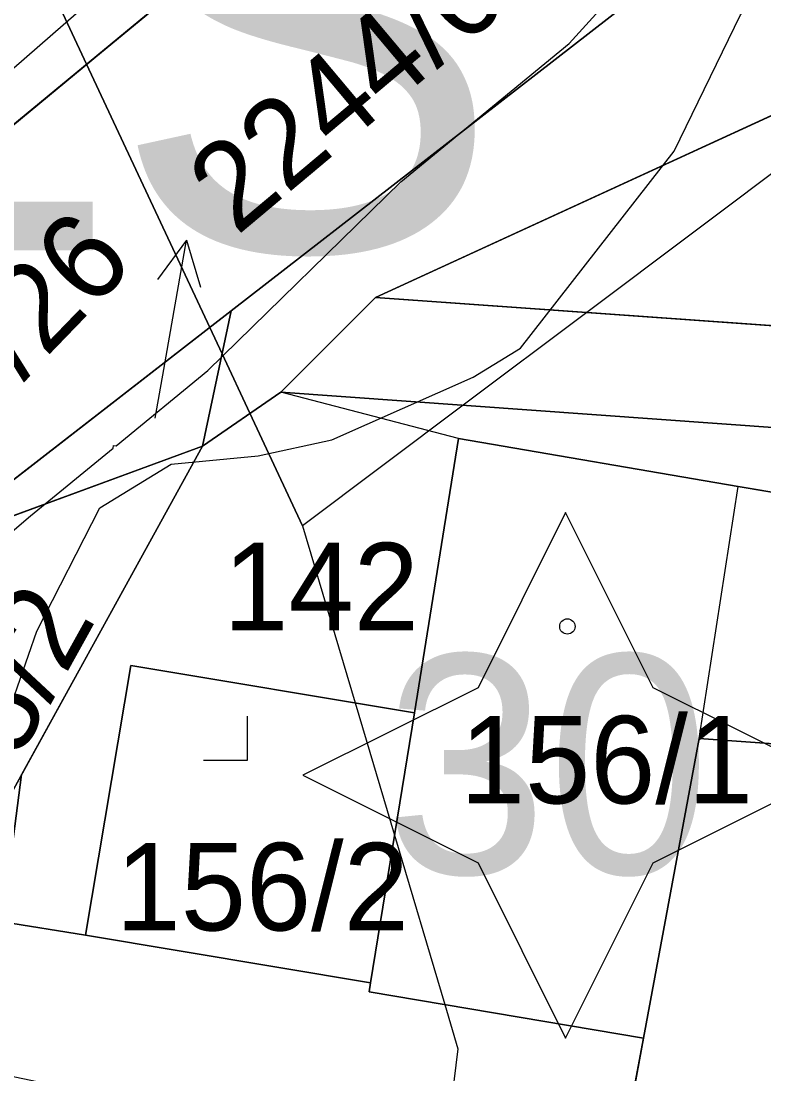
# Model space of a CAD drawing. Extents: x -706130 to -698555, y -971544 to -967260.
# Drawn here: x -704362.42 to -704345.46, y -970171.06 to -970147.02 of the extents above; entities that cross this region are included whole.
import ezdxf

# ---------------------------------------------------------------- set-up
doc = ezdxf.new("R2010")
doc.units = 0
for name, color, linetype in [('_Doplněk budov pro zastavěnost', 7, 'Continuous'), ('Architektonicky cenná stavba S', 7, 'Continuous'), ('BPEJ hranice S', 7, 'Continuous'), ('BPEJ I-II trida ochrany S', 7, 'Continuous'), ('Docházková izochrona - BUS S', 7, 'Continuous'), ('Docházková izochrona - VLAK N', 7, 'Continuous'), ('Hranice intravilán', 7, 'Continuous'), ('KN_Budovy', 7, 'Continuous'), ('KN_Budovy_cisla_domovni', 7, 'Continuous'), ('KN_Hranice_parcel', 7, 'Continuous'), ('KN_Hranice_parcel_vnitrni_kresba', 7, 'Continuous'), ('KN_Parcelni cisla', 7, 'Continuous'), ('KN_Parcelni cisla_sipky', 7, 'Continuous'), ('KN_Polygon parcely', 7, 'Continuous'), ('KN_POZEMKY_11_VODNI_PLOCHA', 7, 'Continuous'), ('KN_POZEMKY_13_ZASTAVENA PLOCHA', 7, 'Continuous'), ('KN_POZEMKY_14_OSTATNI PLOCHA', 7, 'Continuous'), ('KN_POZEMKY_7_TTP', 7, 'Continuous'), ('KN_VYUZITI_07_vodni plocha_tok prirozeny', 7, 'Continuous'), ('KN_VYUZITI_13_zastavena plocha_zboreniste', 7, 'Continuous'), ('KN_VYUZITI_23_ostatni plocha_manipulacni plocha', 7, 'Continuous'), ('KN_VYUZITI_26_ostatni plocha_jina plocha', 7, 'Continuous'), ('KN_Značky budov', 7, 'Continuous'), ('KN_Značky kultur', 7, 'Continuous'), ('Plochy smíšené obytné venkovské S', 7, 'Continuous'), ('Plochy vodní a vodnich toku S', 7, 'Continuous'), ('Plochy zeleně sídelní ostatní S', 7, 'Continuous'), ('Regulační bloky v krajině S', 7, 'Continuous'), ('Regulační bloky v krajině S  TIS', 7, 'Continuous'), ('Regulační bloky zastavěné S', 7, 'Continuous'), ('Regulační kódy zastavěné S', 7, 'Continuous'), ('Záplavové území stanovene S', 7, 'Continuous'), ('Záplavového území_aktivní zóna S', 7, 'Continuous')]:
    doc.layers.add(name, color=color, linetype=linetype)

msp = doc.modelspace()

# ---------------------------------------------------------------- linework, layer by layer
at = {"layer": '_Doplněk budov pro zastavěnost'}
for p, q in [((-704356.49, -970155.49), (-704358.28, -970156.72)), ((-704352.43, -970156.55), (-704356.49, -970155.49)), ((-704352.43, -970156.55), (-704356.49, -970155.49)), ((-704353.44, -970162.81), (-704352.43, -970156.55)), ((-704358.28, -970156.72), (-704362.406, -970164.219)), ((-704353.44, -970162.81), (-704359.91, -970161.73)), ((-704354.44, -970168.98), (-704353.44, -970162.81)), ((-704354.44, -970168.98), (-704353.44, -970162.81)), ((-704354.44, -970168.98), (-704353.44, -970162.81)), ((-704360.95, -970167.89), (-704354.44, -970168.98))]:
    msp.add_line(p, q, dxfattribs=at)
for points in [[(-704359.91, -970161.73), (-704360.95, -970167.89), (-704354.44, -970168.98)], [(-704353.44, -970162.81), (-704359.91, -970161.73), (-704360.95, -970167.89), (-704354.44, -970168.98)], [(-704360.95, -970167.89), (-704362.842, -970167.586), (-704362.406, -970164.219)], [(-704362.406, -970164.219), (-704362.842, -970167.586), (-704360.95, -970167.89)]]:
    msp.add_lwpolyline(points, dxfattribs=at)
at = {"layer": 'Architektonicky cenná stavba S'}
msp.add_lwpolyline([(-704349.987, -970158.238), (-704351.987, -970162.238), (-704355.987, -970164.238), (-704351.987, -970166.238), (-704349.987, -970170.238), (-704347.987, -970166.238), (-704343.987, -970164.238), (-704347.987, -970162.238)], close=True, dxfattribs=at)
at = {"layer": 'BPEJ hranice S'}
for points in [[(-704374.745, -970128.973), (-704371.478, -970133.132), (-704362.806, -970143.976), (-704362.45, -970144.737), (-704360.924, -970147.999), (-704358.111, -970154.01), (-704357.83, -970154.611), (-704357.193, -970155.972), (-704355.992, -970158.539), (-704354.792, -970162.584), (-704353.894, -970165.608), (-704352.747, -970169.471), (-704352.447, -970170.482), (-704352.624, -970171.915), (-704354.19, -970184.627), (-704354.367, -970186.056), (-704354.5, -970187.135), (-704355.235, -970193.101), (-704355.864, -970195.572)], [(-704322.312, -970131.353), (-704329.974, -970139.019), (-704330.011, -970139.046), (-704336.737, -970144.092), (-704339.645, -970146.274), (-704344.012, -970149.55), (-704344.613, -970150.001), (-704349.505, -970153.672), (-704352.326, -970155.788), (-704355.992, -970158.539), (-704357.193, -970155.972), (-704357.83, -970154.611), (-704358.111, -970154.01), (-704360.924, -970147.999), (-704362.45, -970144.737), (-704362.806, -970143.976), (-704371.478, -970133.132), (-704374.745, -970128.973)]]:
    msp.add_lwpolyline(points, dxfattribs=at)
at = {"layer": 'BPEJ I-II trida ochrany S'}
for p, q in [((-704346.94, -970163.4), (-704348.21, -970170.24)), ((-704341.29, -970163.8), (-704346.94, -970163.4)), ((-704348.21, -970170.24), (-704348.58, -970172.23))]:
    msp.add_line(p, q, dxfattribs=at)
at = {"layer": 'Docházková izochrona - BUS S'}
msp.add_arc((-704361.829, -969946.93), 400, 155.51821, 17.33949, dxfattribs=at)
at = {"layer": 'Docházková izochrona - VLAK N'}
msp.add_circle((-704165.451, -969778.767), 800, dxfattribs=at)
at = {"layer": 'Hranice intravilán'}
msp.add_lwpolyline([(-704412.95, -970204.59), (-704393.35, -970187.6), (-704381.73, -970177.47), (-704374.49, -970170.08), (-704373.21, -970168.89), (-704369.29, -970169.71), (-704364.61, -970159.05), (-704358.28, -970156.72), (-704356.49, -970155.49), (-704354.33, -970153.33), (-704341.43, -970147.4), (-704333.46, -970132), (-704329.78, -970132.11), (-704329.33, -970118.8)], dxfattribs=at)
at = {"layer": 'KN_Budovy'}
msp.add_lwpolyline([(-704353.44, -970162.81), (-704354.44, -970168.98), (-704354.47, -970169.18), (-704348.21, -970170.24), (-704346.94, -970163.4), (-704346.05, -970157.64), (-704352.43, -970156.55)], close=True, dxfattribs=at)
at = {"layer": 'KN_Hranice_parcel'}
for p, q in [((-704363.85, -970150.42), (-704354.07, -970142.33)), ((-704348.6, -970146.63), (-704357.62, -970153.63)), ((-704354.33, -970153.33), (-704356.49, -970155.49)), ((-704364.61, -970159.05), (-704357.62, -970153.63)), ((-704357.62, -970153.63), (-704358.28, -970156.72)), ((-704356.49, -970155.49), (-704358.28, -970156.72)), ((-704358.28, -970156.72), (-704365.83, -970170.44)), ((-704358.28, -970156.72), (-704364.61, -970159.05)), ((-704353.44, -970162.81), (-704354.44, -970168.98))]:
    msp.add_line(p, q, dxfattribs=at)
for points in [[(-704329.78, -970132.11), (-704333.46, -970132), (-704341.43, -970147.4), (-704354.33, -970153.33)], [(-704330.19, -970144.44), (-704333.4, -970144.27), (-704339.42, -970143.95), (-704339.99, -970149.84), (-704344.58, -970149.51), (-704344.88, -970154), (-704354.33, -970153.33)], [(-704356.49, -970155.49), (-704345.04, -970156.31), (-704345.08, -970156.89), (-704341.66, -970157.23)], [(-704341.58, -970158.4), (-704346.05, -970157.64), (-704352.43, -970156.55), (-704353.44, -970162.81)], [(-704348.21, -970170.24), (-704346.94, -970163.4), (-704341.29, -970163.8)], [(-704354.44, -970168.98), (-704354.47, -970169.18), (-704348.21, -970170.24)], [(-704358.46, -970171.98), (-704353.17, -970173.09), (-704353.08, -970171.88), (-704348.58, -970172.23), (-704348.21, -970170.24)]]:
    msp.add_lwpolyline(points, dxfattribs=at)
at = {"layer": 'KN_Hranice_parcel_vnitrni_kresba'}
msp.add_line((-704346.94, -970163.4), (-704346.05, -970157.64), dxfattribs=at)
at = {"layer": 'KN_Parcelni cisla_sipky'}
for p, q in [((-704358.639, -970152.015), (-704359.306, -970152.914)), ((-704359.16, -970154.97), (-704358.639, -970152.015)), ((-704358.639, -970152.015), (-704358.32, -970153.088)), ((-704359.36, -970156.08), (-704359.16, -970154.97))]:
    msp.add_line(p, q, dxfattribs=at)
at = {"layer": 'KN_Polygon parcely'}
for points in [[(-704363.85, -970150.42), (-704354.07, -970142.33), (-704339.88, -970120.57), (-704330.42, -970104.89), (-704352.52, -970134.61), (-704374.06, -970156.58), (-704372.7, -970158.25)], [(-704358.28, -970156.72), (-704356.49, -970155.49), (-704354.33, -970153.33), (-704341.43, -970147.4), (-704333.46, -970132), (-704329.78, -970132.11), (-704329.33, -970118.8), (-704330.81, -970123.35), (-704332.33, -970124.25), (-704348.6, -970146.63), (-704357.62, -970153.63)], [(-704333.46, -970132), (-704341.43, -970147.4), (-704354.33, -970153.33), (-704344.88, -970154), (-704344.58, -970149.51), (-704339.99, -970149.84), (-704339.42, -970143.95), (-704333.4, -970144.27), (-704330.19, -970144.44), (-704329.78, -970132.11)], [(-704374.41, -970167.89), (-704374.49, -970170.08), (-704373.21, -970168.89), (-704364.61, -970159.05), (-704357.62, -970153.63), (-704348.6, -970146.63), (-704354.07, -970142.33), (-704363.85, -970150.42), (-704374.17, -970161.44), (-704374.26, -970163.76)], [(-704330.19, -970144.44), (-704333.4, -970144.27), (-704339.42, -970143.95), (-704339.99, -970149.84), (-704344.58, -970149.51), (-704344.88, -970154), (-704354.33, -970153.33), (-704356.49, -970155.49), (-704345.04, -970156.31), (-704345.08, -970156.89), (-704341.66, -970157.23), (-704334.37, -970157.78), (-704330.75, -970158.08)], [(-704358.28, -970156.72), (-704357.62, -970153.63), (-704364.61, -970159.05)], [(-704358.28, -970156.72), (-704365.83, -970170.44), (-704358.46, -970171.98), (-704353.17, -970173.09), (-704353.08, -970171.88), (-704348.58, -970172.23), (-704348.21, -970170.24), (-704354.47, -970169.18), (-704354.44, -970168.98), (-704360.95, -970167.89), (-704359.91, -970161.73), (-704353.44, -970162.81), (-704352.43, -970156.55), (-704346.05, -970157.64), (-704341.58, -970158.4), (-704341.66, -970157.23), (-704345.08, -970156.89), (-704345.04, -970156.31), (-704356.49, -970155.49)], [(-704354.44, -970168.98), (-704354.47, -970169.18), (-704348.21, -970170.24), (-704346.94, -970163.4), (-704341.29, -970163.8), (-704341.58, -970158.4), (-704346.05, -970157.64), (-704352.43, -970156.55), (-704353.44, -970162.81)], [(-704364.61, -970159.05), (-704369.29, -970169.71), (-704365.83, -970170.44), (-704358.28, -970156.72)], [(-704359.91, -970161.73), (-704360.95, -970167.89), (-704354.44, -970168.98), (-704353.44, -970162.81)], [(-704335.93, -970168.1), (-704341.29, -970163.8), (-704346.94, -970163.4), (-704348.21, -970170.24), (-704348.58, -970172.23), (-704353.08, -970171.88), (-704353.17, -970173.09), (-704358.46, -970171.98), (-704359.39, -970177.38), (-704360.03, -970185.62), (-704341.59, -970187.04), (-704342.04, -970190.55), (-704336.36, -970192.11), (-704332.12, -970180.63), (-704336.85, -970180.35), (-704336.66, -970177.92), (-704338.67, -970177.79), (-704338.28, -970171.8), (-704336.18, -970171.94)]]:
    msp.add_lwpolyline(points, close=True, dxfattribs=at)
at = {"layer": 'KN_POZEMKY_11_VODNI_PLOCHA'}
for p, q in [((-704363.85, -970150.42), (-704354.07, -970142.33)), ((-704348.6, -970146.63), (-704357.62, -970153.63)), ((-704357.62, -970153.63), (-704364.61, -970159.05))]:
    msp.add_line(p, q, dxfattribs=at)
at = {"layer": 'KN_POZEMKY_13_ZASTAVENA PLOCHA'}
for p, q in [((-704356.49, -970155.49), (-704354.33, -970153.33)), ((-704354.33, -970153.33), (-704344.88, -970154)), ((-704345.04, -970156.31), (-704356.49, -970155.49)), ((-704353.44, -970162.81), (-704352.43, -970156.55)), ((-704352.43, -970156.55), (-704346.05, -970157.64)), ((-704346.05, -970157.64), (-704341.58, -970158.4)), ((-704360.95, -970167.89), (-704359.91, -970161.73)), ((-704359.91, -970161.73), (-704353.44, -970162.81)), ((-704353.44, -970162.81), (-704354.44, -970168.98)), ((-704354.44, -970168.98), (-704353.44, -970162.81)), ((-704346.94, -970163.4), (-704348.21, -970170.24)), ((-704341.29, -970163.8), (-704346.94, -970163.4)), ((-704354.44, -970168.98), (-704360.95, -970167.89)), ((-704354.47, -970169.18), (-704354.44, -970168.98)), ((-704348.21, -970170.24), (-704354.47, -970169.18))]:
    msp.add_line(p, q, dxfattribs=at)
at = {"layer": 'KN_POZEMKY_14_OSTATNI PLOCHA'}
for p, q in [((-704354.07, -970142.33), (-704363.85, -970150.42)), ((-704357.62, -970153.63), (-704348.6, -970146.63)), ((-704341.43, -970147.4), (-704354.33, -970153.33)), ((-704354.33, -970153.33), (-704341.43, -970147.4)), ((-704354.33, -970153.33), (-704356.49, -970155.49)), ((-704344.88, -970154), (-704354.33, -970153.33)), ((-704364.61, -970159.05), (-704357.62, -970153.63)), ((-704358.28, -970156.72), (-704357.62, -970153.63)), ((-704357.62, -970153.63), (-704358.28, -970156.72)), ((-704358.28, -970156.72), (-704356.49, -970155.49)), ((-704356.49, -970155.49), (-704358.28, -970156.72)), ((-704356.49, -970155.49), (-704345.04, -970156.31)), ((-704352.43, -970156.55), (-704353.44, -970162.81)), ((-704346.05, -970157.64), (-704352.43, -970156.55)), ((-704365.83, -970170.44), (-704358.28, -970156.72)), ((-704358.28, -970156.72), (-704365.83, -970170.44)), ((-704358.28, -970156.72), (-704364.61, -970159.05)), ((-704364.61, -970159.05), (-704358.28, -970156.72)), ((-704341.58, -970158.4), (-704346.05, -970157.64)), ((-704359.91, -970161.73), (-704360.95, -970167.89)), ((-704353.44, -970162.81), (-704359.91, -970161.73)), ((-704360.95, -970167.89), (-704354.44, -970168.98)), ((-704354.44, -970168.98), (-704354.47, -970169.18)), ((-704354.47, -970169.18), (-704348.21, -970170.24)), ((-704348.21, -970170.24), (-704348.58, -970172.23))]:
    msp.add_line(p, q, dxfattribs=at)
at = {"layer": 'KN_POZEMKY_7_TTP'}
for p, q in [((-704348.21, -970170.24), (-704346.94, -970163.4)), ((-704346.94, -970163.4), (-704341.29, -970163.8)), ((-704348.58, -970172.23), (-704348.21, -970170.24))]:
    msp.add_line(p, q, dxfattribs=at)
at = {"layer": 'KN_VYUZITI_07_vodni plocha_tok prirozeny'}
for p, q in [((-704363.85, -970150.42), (-704354.07, -970142.33)), ((-704348.6, -970146.63), (-704357.62, -970153.63)), ((-704357.62, -970153.63), (-704364.61, -970159.05))]:
    msp.add_line(p, q, dxfattribs=at)
at = {"layer": 'KN_VYUZITI_13_zastavena plocha_zboreniste'}
for p, q in [((-704360.95, -970167.89), (-704359.91, -970161.73)), ((-704359.91, -970161.73), (-704353.44, -970162.81)), ((-704353.44, -970162.81), (-704354.44, -970168.98)), ((-704354.44, -970168.98), (-704360.95, -970167.89))]:
    msp.add_line(p, q, dxfattribs=at)
at = {"layer": 'KN_VYUZITI_23_ostatni plocha_manipulacni plocha'}
for p, q in [((-704354.33, -970153.33), (-704341.43, -970147.4)), ((-704344.88, -970154), (-704354.33, -970153.33)), ((-704358.28, -970156.72), (-704356.49, -970155.49)), ((-704356.49, -970155.49), (-704345.04, -970156.31)), ((-704352.43, -970156.55), (-704353.44, -970162.81)), ((-704346.05, -970157.64), (-704352.43, -970156.55)), ((-704365.83, -970170.44), (-704358.28, -970156.72)), ((-704341.58, -970158.4), (-704346.05, -970157.64)), ((-704359.91, -970161.73), (-704360.95, -970167.89)), ((-704353.44, -970162.81), (-704359.91, -970161.73)), ((-704360.95, -970167.89), (-704354.44, -970168.98)), ((-704354.44, -970168.98), (-704354.47, -970169.18)), ((-704354.47, -970169.18), (-704348.21, -970170.24)), ((-704348.21, -970170.24), (-704348.58, -970172.23))]:
    msp.add_line(p, q, dxfattribs=at)
at = {"layer": 'KN_VYUZITI_26_ostatni plocha_jina plocha'}
for p, q in [((-704354.07, -970142.33), (-704363.85, -970150.42)), ((-704357.62, -970153.63), (-704348.6, -970146.63)), ((-704341.43, -970147.4), (-704354.33, -970153.33)), ((-704354.33, -970153.33), (-704356.49, -970155.49)), ((-704364.61, -970159.05), (-704357.62, -970153.63)), ((-704358.28, -970156.72), (-704357.62, -970153.63)), ((-704357.62, -970153.63), (-704358.28, -970156.72)), ((-704356.49, -970155.49), (-704358.28, -970156.72)), ((-704358.28, -970156.72), (-704365.83, -970170.44)), ((-704358.28, -970156.72), (-704364.61, -970159.05)), ((-704364.61, -970159.05), (-704358.28, -970156.72))]:
    msp.add_line(p, q, dxfattribs=at)
at = {"layer": 'KN_Značky budov'}
msp.add_circle((-704349.947, -970160.839), 0.175, dxfattribs=at)
at = {"layer": 'KN_Značky kultur'}
for p, q in [((-704357.25, -970163.89), (-704357.25, -970162.89)), ((-704358.251, -970163.89), (-704357.25, -970163.89))]:
    msp.add_line(p, q, dxfattribs=at)
at = {"layer": 'Plochy smíšené obytné venkovské S'}
for p, q in [((-704348.6, -970146.63), (-704357.62, -970153.63)), ((-704357.62, -970153.63), (-704364.61, -970159.05))]:
    msp.add_line(p, q, dxfattribs=at)
at = {"layer": 'Plochy vodní a vodnich toku S'}
for p, q in [((-704354.07, -970142.33), (-704363.85, -970150.42)), ((-704357.62, -970153.63), (-704348.6, -970146.63)), ((-704364.61, -970159.05), (-704357.62, -970153.63))]:
    msp.add_line(p, q, dxfattribs=at)
at = {"layer": 'Plochy zeleně sídelní ostatní S'}
msp.add_line((-704363.85, -970150.42), (-704354.07, -970142.33), dxfattribs=at)
at = {"layer": 'Regulační bloky v krajině S'}
for p, q in [((-704354.07, -970142.33), (-704363.85, -970150.42)), ((-704357.62, -970153.63), (-704348.6, -970146.63)), ((-704364.61, -970159.05), (-704357.62, -970153.63))]:
    msp.add_line(p, q, dxfattribs=at)
at = {"layer": 'Regulační bloky v krajině S  TIS'}
for p, q in [((-704354.07, -970142.33), (-704363.85, -970150.42)), ((-704357.62, -970153.63), (-704348.6, -970146.63)), ((-704364.61, -970159.05), (-704357.62, -970153.63))]:
    msp.add_line(p, q, dxfattribs=at)
at = {"layer": 'Regulační bloky zastavěné S'}
for p, q in [((-704363.85, -970150.42), (-704354.07, -970142.33)), ((-704348.6, -970146.63), (-704357.62, -970153.63)), ((-704357.62, -970153.63), (-704364.61, -970159.05))]:
    msp.add_line(p, q, dxfattribs=at)
at = {"layer": 'Záplavové území stanovene S'}
msp.add_lwpolyline([(-704371.331, -970168.625), (-704370.69, -970167.875), (-704368.665, -970167.125), (-704365.875, -970165.7), (-704363.707, -970164.793), (-704362.822, -970163.139), (-704362.056, -970160.944), (-704360.62, -970158.13), (-704358.991, -970157.135), (-704357.003, -970156.945), (-704355.326, -970156.576), (-704352.097, -970155.145), (-704351.019, -970154.481), (-704347.512, -970149.988), (-704345.993, -970146.875), (-704342.948, -970142.948), (-704340.029, -970138.721), (-704336.28, -970132.72), (-704335.273, -970129.727)], dxfattribs=at)
at = {"layer": 'Záplavového území_aktivní zóna S'}
for points in [[(-704371.875, -970167.625), (-704370.5, -970166.125), (-704369.205, -970164.747), (-704364.64, -970160.389), (-704362.202, -970158.314), (-704360.314, -970156.765), (-704360.306, -970156.705), (-704360.25, -970156.713), (-704358.156, -970154.995), (-704353.747, -970150.689), (-704349.908, -970147.525), (-704345.24, -970142.389), (-704338.652, -970133.571), (-704336.006, -970129.162)], [(-704346.375, -970131.125), (-704346.688, -970132.062), (-704348.5, -970134.75), (-704350.312, -970136.062), (-704350.5, -970136.625), (-704351.25, -970137.5), (-704351.688, -970138.688), (-704352.312, -970139.562), (-704358.368, -970144.407), (-704363.245, -970148.66), (-704367.913, -970152.602), (-704373.25, -970157.875), (-704374.875, -970159.625), (-704376.5, -970162.625), (-704379.5, -970165.875), (-704379.5, -970166.125), (-704381, -970167.75), (-704381.875, -970168.375), (-704383.75, -970169.125), (-704386.25, -970171.312), (-704388.688, -970173.938), (-704392.562, -970177.812), (-704399.037, -970181.755)]]:
    msp.add_lwpolyline(points, dxfattribs=at)

# ---------------------------------------------------------------- texts
at = {"layer": 'KN_Budovy_cisla_domovni'}
msp.add_text('30', height=5, dxfattribs=at).set_placement((-704354.12, -970166.484))
at = {"layer": 'KN_Parcelni cisla'}
for s, rotation, p in [('2244/6', 40, (-704357.498, -970151.936)), ('1958/26', 46, (-704366.508, -970159.53)), ('1678/2', 61, (-704364.656, -970167.822))]:
    msp.add_text(s, height=2, rotation=rotation, dxfattribs=at).set_placement(p)
for s, p in [('142', (-704357.8, -970160.929)), ('156/1', (-704352.4, -970164.88)), ('156/2', (-704360.26, -970167.78))]:
    msp.add_text(s, height=2, dxfattribs=at).set_placement(p)
at = {"layer": 'Regulační kódy zastavěné S'}
msp.add_text('ZS', height=10, dxfattribs=at).set_placement((-704368.535, -970152.25))

doc.saveas('drawing.dxf')
